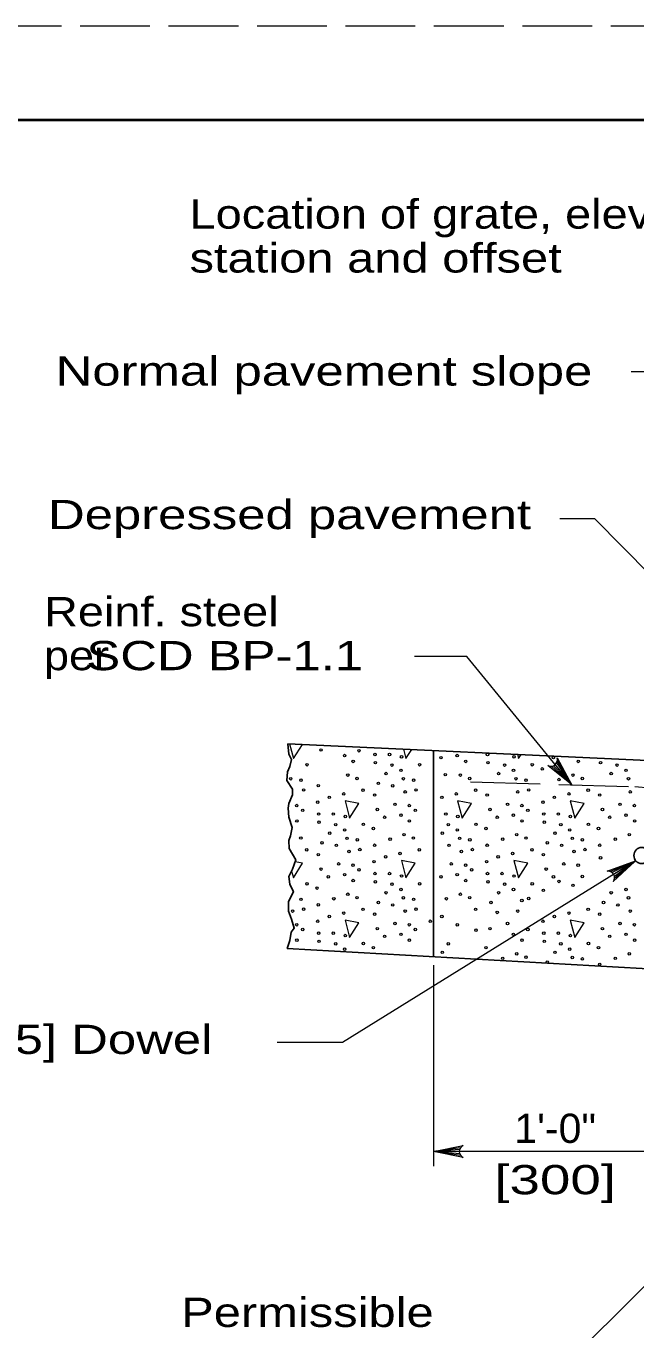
# Model space of a CAD drawing. Extents: x 1352.5 to 1386.5, y 735.9 to 779.9.
# Drawn here: x 1372.16 to 1375.42, y 772.96 to 779.92 of the extents above; entities that cross this region are included whole.
import ezdxf
from ezdxf.enums import TextEntityAlignment as Align

# ---------------------------------------------------------------- set-up
doc = ezdxf.new("R2010")
doc.units = 0
doc.header["$LTSCALE"] = 0.062
doc.linetypes.add('LONG_DASHED', pattern=[7.5, 6, -1.5])
doc.layers.add('1', color=7, linetype='Continuous', lineweight=13)

msp = doc.modelspace()

# ---------------------------------------------------------------- linework, layer by layer
at = {"layer": '1', "lineweight": 25}
msp.add_line((1354.513, 779.41967), (1386.013, 779.41967), dxfattribs=at)
at = {"layer": '1'}
for p, q in [((1374.99533, 775.987), (1375.07475, 775.8705)), ((1374.999, 775.99717), (1375.07475, 775.8705)), ((1374.96733, 775.96883), (1375.07475, 775.8705)), ((1374.97817, 775.97142), (1375.07475, 775.8705)), ((1374.987, 775.97675), (1375.07475, 775.8705)), ((1375.281, 775.40675), (1375.41683, 775.4645)), ((1375.29058, 775.40167), (1375.41683, 775.4645)), ((1375.29958, 775.392), (1375.41683, 775.4645)), ((1375.30367, 775.38258), (1375.41683, 775.4645)), ((1375.30475, 775.3715), (1375.41683, 775.4645)), ((1374.33825, 774.907), (1374.33825, 773.8335)), ((1374.4825, 773.93233), (1374.33825, 773.91217)), ((1374.47758, 773.92233), (1374.33825, 773.91217)), ((1374.47617, 773.91217), (1374.33825, 773.91217)), ((1374.47867, 773.89917), (1374.33825, 773.91217)), ((1374.48417, 773.88983), (1374.33825, 773.91217)), ((1375.57867, 773.91217), (1374.33825, 773.91217))]:
    msp.add_line(p, q, dxfattribs=at)
at = {"layer": '1', "linetype": 'LONG_DASHED'}
msp.add_lwpolyline([(1352.513, 757.91967), (1386.513, 757.91967), (1386.513, 779.91967), (1352.513, 779.91967)], close=True, dxfattribs=at)
at = {"layer": '1', "lineweight": 40}
msp.add_lwpolyline([(1354.513, 779.41967), (1386.013, 779.41967), (1386.013, 758.41967), (1354.513, 758.41967)], close=True, dxfattribs=at)
msp.add_lwpolyline([(1354.513, 779.41967), (1386.013, 779.41967), (1386.013, 758.41967), (1354.513, 758.41967)], close=True, dxfattribs=at)
at = {"layer": '1'}
for points in [[(1376.97058, 776.00042), (1375.67183, 778.07408), (1375.39275, 778.07408)], [(1376.53433, 775.93808), (1375.19883, 777.28867), (1375.01275, 777.28867)], [(1375.07475, 775.8705), (1374.5165, 776.55408), (1374.23733, 776.55408)], [(1373.56983, 776.08808), (1373.5905, 776.00925), (1373.63867, 776.08492)], [(1374.178, 776.06008), (1374.19133, 776.00925), (1374.22233, 776.05808)], [(1374.786, 776.03192), (1374.792, 776.00925), (1374.806, 776.03117)], [(1374.99783, 776.01358), (1375.07475, 775.8705), (1374.94875, 775.973)], [(1375.41683, 775.4645), (1373.8535, 774.49417), (1373.5045, 774.49417)], [(1373.58117, 775.409), (1373.5905, 775.37325), (1373.64, 775.45108), (1373.59992, 775.45883)], [(1375.26458, 775.40783), (1375.41683, 775.4645), (1375.29808, 775.35367)], [(1376.80792, 774.53058), (1375.03217, 772.76333), (1376.67692, 771.33608)], [(1374.49758, 773.88025), (1374.33825, 773.91217), (1374.49758, 773.944)]]:
    msp.add_lwpolyline(points, dxfattribs=at)
at = {"layer": '1', "lineweight": 25}
for points in [[(1373.56083, 776.0885), (1373.56675, 776.03308), (1373.58117, 776.00542), (1373.57092, 775.96783), (1373.55908, 775.93842), (1373.55567, 775.89192), (1373.58625, 775.84633), (1373.58617, 775.816), (1373.56667, 775.7695), (1373.56242, 775.7445), (1373.56667, 775.69633), (1373.58367, 775.64092), (1373.576, 775.59625), (1373.56575, 775.573), (1373.56908, 775.53017), (1373.60308, 775.46842), (1373.58608, 775.41842), (1373.56575, 775.38), (1373.57167, 775.33892), (1373.59117, 775.29867), (1373.56483, 775.24683), (1373.56392, 775.19508), (1373.58092, 775.15208), (1373.59533, 775.10483), (1373.57833, 775.08342), (1373.57233, 775.03783), (1373.55775, 774.99583), (1375.57867, 774.88233)], [(1376.337, 775.91417), (1375.48067, 776), (1373.56083, 776.0885)], [(1374.33825, 774.952), (1374.33825, 775.80917), (1374.33825, 776.05267)]]:
    msp.add_lwpolyline(points, dxfattribs=at)
at = {"layer": '1', "linetype": 'LONG_DASHED'}
msp.add_lwpolyline([(1374.53508, 775.88617), (1375.41325, 775.85967), (1376.10083, 775.8045)], dxfattribs=at)
at = {"layer": '1'}
for points in [[(1373.86658, 775.78342), (1373.89092, 775.69125), (1373.94042, 775.76908)], [(1374.46733, 775.78342), (1374.49167, 775.69125), (1374.54108, 775.76908)], [(1375.06817, 775.78342), (1375.09242, 775.69125), (1375.14183, 775.76908)], [(1374.167, 775.46542), (1374.19133, 775.37325), (1374.24075, 775.45108)], [(1374.76775, 775.46542), (1374.792, 775.37325), (1374.8415, 775.45108)], [(1373.86658, 775.14742), (1373.89092, 775.05517), (1373.94042, 775.133)], [(1375.06817, 775.14742), (1375.09242, 775.05517), (1375.14183, 775.133)]]:
    msp.add_lwpolyline(points, close=True, dxfattribs=at)
for centre, start, end in [((1374.96509, 776.00321), 241.65315, 17.47928), ((1375.27042, 775.37394), 323.8061, 99.63222), ((1374.51045, 773.91218), 112.08782, 247.91395)]:
    msp.add_arc(centre, 0.03438, start, end, dxfattribs=at)
for centre in [(1373.73826, 776.05559), (1373.94077, 776.0513), (1373.66362, 775.97656), (1373.86397, 776.02554), (1373.90968, 775.99432), (1374.02593, 776.03153), (1374.02833, 775.98775), (1374.10382, 776.03153), (1374.11679, 775.97487), (1374.16785, 776.01865), (1374.26438, 775.97656), (1374.37797, 776.01435), (1374.46473, 776.02554), (1374.51044, 775.99432), (1374.62668, 776.03153), (1374.62909, 775.98775), (1374.71755, 775.97487), (1374.76861, 776.01865), (1374.86513, 775.97656), (1374.97873, 776.01435), (1375.11119, 775.99432), (1375.22984, 775.98775), (1375.31831, 775.97487), (1373.88129, 775.92133), (1373.93076, 775.90331), (1374.0851, 775.92934), (1374.1646, 775.94651), (1374.40123, 775.92345), (1374.48205, 775.92133), (1374.53151, 775.90331), (1374.68586, 775.92934), (1374.76536, 775.94651), (1374.91865, 775.95425), (1375.08281, 775.92133), (1375.13227, 775.90331), (1375.28662, 775.92934), (1375.36612, 775.94651), (1373.57686, 775.90188), (1373.63118, 775.89409), (1373.64494, 775.84178), (1373.72364, 775.86489), (1373.96235, 775.84061), (1374.0443, 775.87755), (1374.1208, 775.86409), (1374.17762, 775.90188), (1374.23194, 775.89409), (1374.2457, 775.84178), (1374.5631, 775.84061), (1374.77837, 775.90188), (1374.83269, 775.89409), (1374.84646, 775.84178), (1375.00816, 775.89732), (1375.16386, 775.84061), (1375.37913, 775.90188), (1373.72069, 775.77706), (1373.78227, 775.80282), (1373.85937, 775.82084), (1374.02402, 775.81485), (1374.13271, 775.76508), (1374.18728, 775.83144), (1374.38303, 775.80282), (1374.46012, 775.82084), (1374.62478, 775.81485), (1374.73347, 775.76508), (1374.78804, 775.83144), (1374.92221, 775.77706), (1374.98378, 775.80282), (1375.06088, 775.82084), (1375.22554, 775.81485), (1375.33423, 775.76508), (1375.38879, 775.83144), (1373.6085, 775.75846), (1373.64039, 775.73328), (1373.72555, 775.71351), (1373.80344, 775.71351), (1373.86748, 775.70063), (1374.03864, 775.73757), (1374.07759, 775.69634), (1374.16435, 775.70752), (1374.20926, 775.75846), (1374.24115, 775.73328), (1374.4042, 775.71351), (1374.46823, 775.70063), (1374.6394, 775.73757), (1374.67835, 775.69634), (1374.76511, 775.70752), (1374.81001, 775.75846), (1374.8419, 775.73328), (1374.92706, 775.71351), (1375.00496, 775.71351), (1375.06899, 775.70063), (1375.24016, 775.73757), (1375.27911, 775.69634), (1375.36587, 775.70752), (1375.41077, 775.75846), (1373.6093, 775.6763), (1373.72795, 775.66973), (1373.81641, 775.65685), (1373.86422, 775.6285), (1373.964, 775.65855), (1374.01751, 775.63623), (1374.21006, 775.6763), (1374.41717, 775.65685), (1374.46498, 775.6285), (1374.56476, 775.65855), (1374.61827, 775.63623), (1374.81082, 775.6763), (1374.92947, 775.66973), (1375.01793, 775.65685), (1375.06574, 775.6285), (1375.16551, 775.65855), (1375.21903, 775.63623), (1375.41157, 775.6763), (1373.63038, 775.5853), (1373.74392, 775.55954), (1373.78472, 775.61132), (1373.87724, 775.58387), (1373.93156, 775.57608), (1374.10703, 775.57931), (1374.18167, 775.60332), (1374.23113, 775.5853), (1374.38548, 775.61132), (1374.478, 775.58387), (1374.53231, 775.57608), (1374.70779, 775.57931), (1374.78243, 775.60332), (1374.83189, 775.5853), (1374.94544, 775.55954), (1374.98624, 775.61132), (1375.07875, 775.58387), (1375.13307, 775.57608), (1375.30854, 775.57931), (1375.38319, 775.60332), (1373.66197, 775.5226), (1373.72364, 775.49684), (1373.82042, 775.54608), (1373.8869, 775.51343), (1373.94532, 775.52376), (1374.02402, 775.54687), (1374.15974, 775.50283), (1374.26272, 775.5226), (1374.42117, 775.54608), (1374.48766, 775.51343), (1374.54608, 775.52376), (1374.62478, 775.54687), (1374.7605, 775.50283), (1374.86348, 775.5226), (1374.92516, 775.49684), (1375.02193, 775.54608), (1375.08842, 775.51343), (1375.14684, 775.52376), (1375.22554, 775.54687), (1373.73826, 775.41956), (1373.83233, 775.44707), (1373.90888, 775.44044), (1374.02107, 775.45905), (1374.08265, 775.48481), (1374.43309, 775.44707), (1374.50964, 775.44044), (1374.62183, 775.45905), (1374.6834, 775.48481), (1374.93978, 775.41956), (1375.03385, 775.44707), (1375.11039, 775.44044), (1375.22984, 775.47966), (1373.77721, 775.37832), (1373.86397, 775.38951), (1373.90968, 775.35829), (1373.94077, 775.41527), (1374.02593, 775.3955), (1374.02833, 775.35172), (1374.10382, 775.3955), (1374.16785, 775.38262), (1374.37797, 775.37832), (1374.46473, 775.38951), (1374.51044, 775.35829), (1374.54153, 775.41527), (1374.62668, 775.3955), (1374.62909, 775.35172), (1374.70458, 775.3955), (1374.76861, 775.38262), (1374.97873, 775.37832), (1375.00816, 775.35378), (1375.13227, 775.37981), (1373.66362, 775.34053), (1373.71714, 775.31822), (1373.88129, 775.2853), (1374.0851, 775.29331), (1374.11679, 775.33884), (1374.1646, 775.31048), (1374.26438, 775.34053), (1374.48205, 775.2853), (1374.68586, 775.29331), (1374.71755, 775.33884), (1374.76536, 775.31048), (1374.86513, 775.34053), (1374.92516, 775.30593), (1375.08281, 775.33309), (1375.28662, 775.29331), (1375.36612, 775.31048), (1373.63118, 775.25806), (1373.72364, 775.22886), (1373.80665, 775.26129), (1373.93076, 775.26728), (1374.0443, 775.24152), (1374.1208, 775.22806), (1374.17762, 775.26585), (1374.23194, 775.25806), (1374.40741, 775.26129), (1374.53151, 775.26728), (1374.64506, 775.24152), (1374.81001, 775.25191), (1374.84646, 775.26278), (1375.24581, 775.24152), (1375.32231, 775.22806), (1375.37913, 775.26585), (1373.58652, 775.19541), (1373.64494, 775.20575), (1373.72069, 775.14103), (1373.78227, 775.16679), (1373.85937, 775.18481), (1373.96235, 775.20458), (1374.02402, 775.17882), (1374.18728, 775.19541), (1374.2457, 775.20575), (1374.32145, 775.14103), (1374.38303, 775.16679), (1374.5631, 775.20458), (1374.67835, 775.18825), (1374.78804, 775.19541), (1374.92221, 775.14103), (1374.98378, 775.16679), (1375.06088, 775.18481), (1375.16386, 775.20458), (1375.22554, 775.17882), (1375.38879, 775.19541), (1373.6085, 775.12243), (1373.64039, 775.09725), (1373.72555, 775.07748), (1373.80344, 775.07748), (1374.03864, 775.10155), (1374.13271, 775.12905), (1374.16435, 775.07149), (1374.20926, 775.12243), (1374.24115, 775.09725), (1374.46498, 775.12195), (1374.56476, 775.09343), (1374.6394, 775.10155), (1374.73347, 775.12905), (1374.76511, 775.07149), (1374.8419, 775.09725), (1374.92706, 775.07748), (1375.00496, 775.07748), (1375.24016, 775.10155), (1375.33423, 775.12905), (1375.36587, 775.07149), (1375.41077, 775.12243), (1373.6093, 775.04027), (1373.72795, 775.0337), (1373.81641, 775.02082), (1373.86748, 775.0646), (1373.964, 775.02252), (1374.01751, 775.0002), (1374.07759, 775.06031), (1374.21006, 775.04027), (1374.41717, 775.02082), (1374.61827, 775.0002), (1374.81082, 775.04027), (1374.92947, 775.0337), (1375.01793, 775.02082), (1375.06899, 775.0646), (1375.16551, 775.02252), (1375.21903, 775.0002), (1375.27911, 775.06031), (1375.41157, 775.04027), (1373.86422, 774.99247), (1374.38548, 774.97529), (1374.70779, 774.94328), (1374.78243, 774.96729), (1374.83189, 774.94927), (1374.98624, 774.97529), (1375.06574, 774.99247), (1375.07875, 774.94784), (1375.13307, 774.94005), (1375.30854, 774.94328), (1375.38319, 774.96729), (1374.94544, 774.92351), (1375.22554, 774.91084)]:
    msp.add_ellipse(centre, major_axis=(0, 0.0068), ratio=0.944544, dxfattribs=at)
at = {"layer": '1', "lineweight": 25}
msp.add_ellipse((1375.44871, 775.49197), major_axis=(0, 0.04284), ratio=0.944544, dxfattribs=at)

# ---------------------------------------------------------------- texts
at = {"layer": '1'}
for s, width, p in [('Location of grate, elev.,', 1.2, (1373.03675, 778.83858)), ('station and offset', 1.25, (1373.03675, 778.60392)), ('Normal pavement slope', 1.3, (1372.322, 778.00042)), ('Depressed pavement', 1.3, (1372.28117, 777.23425)), ('Reinf. steel', 1.2, (1372.25983, 776.716)), ('   SCD BP-1.1', 1.3, (1372.25983, 776.48133)), ('per', 1.15, (1372.25983, 776.48133)), ('1" [25] Dowel', 1.3, (1371.55483, 774.43267)), ('Permissible', 1.25, (1372.99183, 772.9755))]:
    msp.add_text(s, height=0.156, dxfattribs=dict(at, width=width)).set_placement(p)
for s, width, p in [('1\'-0"', 1.05, (1374.98762, 773.95775)), ('[300]', 1.4, (1374.98767, 773.68375))]:
    msp.add_text(s, height=0.156, dxfattribs=dict(at, width=width)).set_placement(p, align=Align.CENTER)

doc.saveas('drawing.dxf')
